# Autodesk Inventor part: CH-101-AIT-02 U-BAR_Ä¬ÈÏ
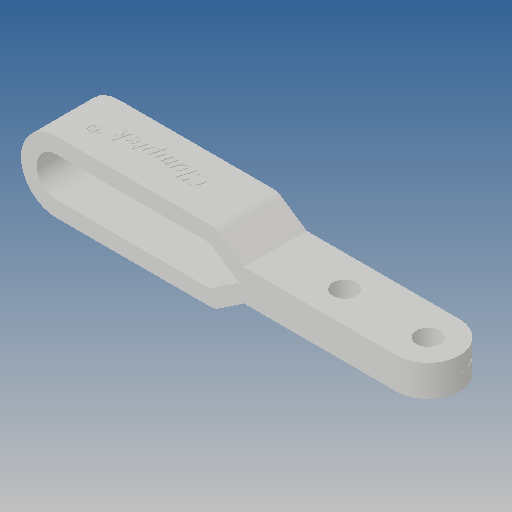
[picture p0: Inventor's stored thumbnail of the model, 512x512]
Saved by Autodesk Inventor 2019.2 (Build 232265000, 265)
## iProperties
Created: 2010-06
Part Number: CH-101-AIT-02 U-BAR_Ä¬ÈÏ
Material: Ogólny
Document SubType Name: Modeling
Designer: CADENGINEERING4
Density: 1 g/cm^3
Appearance: Domyślna
Author: CADENGINEERING4
Revision Number: ÈÎºÎ
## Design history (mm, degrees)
feature "NONE"
feature "NONE:1"
node "Bryła1"
node "Bryła2"
